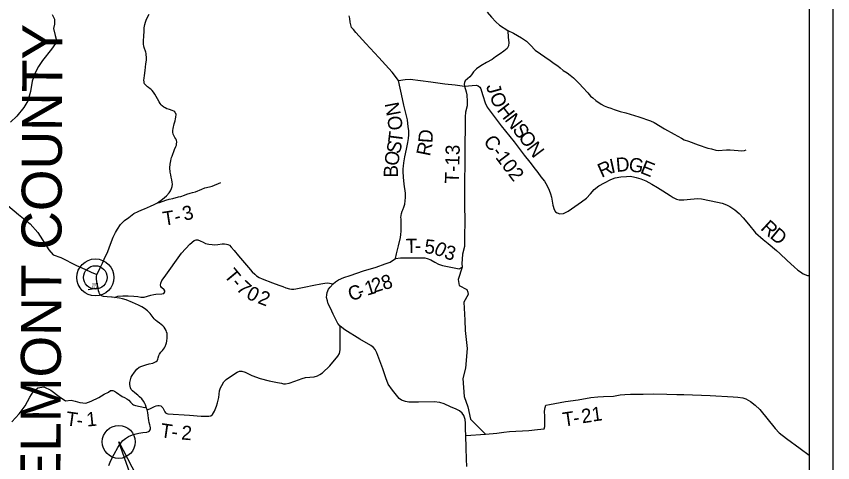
# Model space of a CAD drawing. Extents: x 0 to 2329303, y 0 to 694397.
# Drawn here: x 5.532 to 9, y 16.215 to 18.113 of the extents above; entities that cross this region are included whole.
import ezdxf

# ---------------------------------------------------------------- set-up
doc = ezdxf.new("R2010")
doc.units = 0
for name, color, linetype in [('GM_X_County', 7, 'Continuous'), ('GM_X_County_Road', 7, 'Continuous'), ('GM_X_County_Road_Text', 7, 'Continuous'), ('GM_X_State_Route', 7, 'Continuous'), ('GM_X_Township_Road', 7, 'Continuous'), ('GM_X_Township_Road_Text', 7, 'Continuous'), ('GM_X_Township_ROW', 7, 'Continuous'), ('GM_X_Township_Subdivision', 7, 'Continuous'), ('GM_X_Township_Subdivision_Text', 7, 'Continuous'), ('GM_X_Unincorporated', 7, 'Continuous'), ('SH_Data', 7, 'Continuous')]:
    doc.layers.add(name, color=color, linetype=linetype)

msp = doc.modelspace()

# ---------------------------------------------------------------- linework, layer by layer
at = {"layer": 'GM_X_County_Road'}
for points in [[(7.1555, 17.8397), (7.1292, 17.8753), (7.072, 17.9377), (7.0165, 17.9975), (6.9751, 18.0441), (6.964, 18.056), (6.9564, 18.0648), (6.9527, 18.0762), (6.9503, 18.0875), (6.9493, 18.1033), (6.9464, 18.1149)], [(7.446, 16.1983), (7.4453, 16.2296), (7.4436, 16.2777), (7.4424, 16.3304), (7.441, 16.3567), (7.4406, 16.3821), (7.4394, 16.3983), (7.4336, 16.4146), (7.4262, 16.4256), (7.4149, 16.4351), (7.4011, 16.4417), (7.3771, 16.4527), (7.3502, 16.4656), (7.3312, 16.4703), (7.3066, 16.4727), (7.2409, 16.4719), (7.2135, 16.4721), (7.1992, 16.4724), (7.1853, 16.4746), (7.169, 16.4809), (7.1588, 16.4877), (7.1472, 16.5019), (7.1309, 16.5225), (7.1123, 16.5487), (7.1018, 16.5754), (7.089, 16.613), (7.0634, 16.6822), (7.0561, 16.6952), (7.0499, 16.7041), (7.0386, 16.7129), (6.9915, 16.7405), (6.9285, 16.7802), (6.9078, 16.7952), (6.8975, 16.8071), (6.8912, 16.82), (6.8782, 16.8458), (6.8671, 16.8713), (6.857, 16.8906), (6.8537, 16.9026), (6.8505, 16.9169), (6.8512, 16.9282), (6.8533, 16.9385), (6.8557, 16.9451), (6.859, 16.952), (6.865, 16.9612), (6.8777, 16.9755), (6.8878, 16.9833), (6.9011, 16.9919), (6.9236, 17.0015), (6.9511, 17.01), (7.0076, 17.0297), (7.0613, 17.0466), (7.0998, 17.0601), (7.1197, 17.0679), (7.1429, 17.0828), (7.1471, 17.102), (7.1557, 17.1373), (7.1641, 17.1723), (7.1658, 17.1855), (7.1666, 17.1994), (7.1666, 17.2276), (7.1665, 17.2515), (7.1662, 17.2577), (7.1668, 17.266), (7.1683, 17.2735), (7.1711, 17.2845), (7.1737, 17.2902), (7.1784, 17.3012), (7.182, 17.314), (7.1844, 17.328), (7.1858, 17.342), (7.1855, 17.3612), (7.1805, 17.3984), (7.1765, 17.4282), (7.1754, 17.453), (7.1754, 17.4646), (7.1768, 17.4753), (7.1786, 17.4895), (7.1834, 17.515), (7.1896, 17.5471), (7.1958, 17.5767), (7.1981, 17.5927), (7.1991, 17.6081), (7.1993, 17.6265), (7.1975, 17.6425), (7.1936, 17.6725), (7.1848, 17.7115), (7.179, 17.7354), (7.169, 17.7814), (7.1629, 17.807), (7.1555, 17.8397)], [(7.1555, 17.8397), (7.184, 17.8445), (7.2059, 17.8446), (7.293, 17.8346), (7.3533, 17.8256), (7.3964, 17.8205), (7.4365, 17.8157), (7.4857, 17.8195), (7.4944, 17.8169), (7.5015, 17.8116), (7.5061, 17.804), (7.5087, 17.7936), (7.5147, 17.7752), (7.5243, 17.7446), (7.5329, 17.726), (7.5496, 17.7041), (7.5924, 17.6475), (7.6476, 17.5783), (7.69, 17.5222), (7.7135, 17.493), (7.7367, 17.463), (7.7477, 17.4482), (7.7609, 17.4303), (7.7762, 17.4117), (7.7877, 17.3924), (7.7957, 17.3733), (7.8016, 17.3577), (7.8053, 17.3435), (7.8107, 17.3098), (7.817, 17.2911), (7.8224, 17.2817), (7.8294, 17.2763), (7.8413, 17.273), (7.8563, 17.2746), (7.8758, 17.2835), (7.9331, 17.3234), (7.9547, 17.3388), (7.9711, 17.3571), (7.9869, 17.3766), (8.0072, 17.3914), (8.0305, 17.405), (8.0572, 17.4193), (8.0765, 17.4251), (8.0999, 17.4296), (8.1238, 17.4321), (8.1396, 17.4326), (8.1536, 17.4307), (8.1647, 17.4276), (8.1857, 17.421), (8.2059, 17.4129), (8.2312, 17.3994), (8.2562, 17.3852), (8.2791, 17.3703), (8.3092, 17.3503), (8.322, 17.3422), (8.3373, 17.3346), (8.3481, 17.3318), (8.3684, 17.3318), (8.396, 17.3356), (8.4273, 17.3373), (8.4423, 17.3359), (8.5114, 17.3226), (8.5307, 17.3183), (8.5488, 17.3108), (8.5628, 17.3041), (8.5839, 17.2896), (8.6027, 17.2743), (8.6193, 17.2555), (8.6419, 17.2286), (8.6724, 17.1923), (8.7045, 17.1629), (8.7253, 17.1465), (8.7613, 17.1171), (8.776, 17.1034), (8.8073, 17.0739), (8.8363, 17.048), (8.8527, 17.0337), (8.8632, 17.0257), (8.8746, 17.0183), (8.8934, 17.0111), (8.9, 17.0099)], [(5.4966, 17.3082), (5.5414, 17.2703), (5.5919, 17.2302), (5.6241, 17.1939), (5.6708, 17.1199), (5.6888, 17.0991), (5.7217, 17.0865), (5.7881, 17.0526), (5.8233, 17.0374), (5.8508, 17.0243), (5.8747, 17.0143)]]:
    msp.add_lwpolyline(points, dxfattribs=at)
at = {"layer": 'GM_X_State_Route'}
for points in [[(6.0651, 17.2894), (6.0765, 17.2943), (6.1027, 17.3056), (6.118, 17.3124), (6.132, 17.3197), (6.1533, 17.3345), (6.1701, 17.3491), (6.1819, 17.3613), (6.1875, 17.3706), (6.1916, 17.3804), (6.194, 17.3883), (6.1954, 17.3986), (6.1947, 17.4069), (6.1929, 17.4168), (6.1901, 17.4287), (6.1881, 17.4387), (6.1863, 17.4504), (6.1852, 17.4679), (6.1861, 17.4839), (6.1871, 17.4916), (6.1883, 17.4987), (6.1902, 17.5066), (6.1918, 17.512), (6.1938, 17.5181), (6.205, 17.5465), (6.2099, 17.5593), (6.2123, 17.5653), (6.2135, 17.5707), (6.2139, 17.5772), (6.2127, 17.5854), (6.2098, 17.5922), (6.2063, 17.5979), (6.2018, 17.6057), (6.1993, 17.6109), (6.1976, 17.6205), (6.1975, 17.6264), (6.199, 17.6358), (6.2034, 17.6553), (6.2065, 17.6686), (6.2086, 17.6773), (6.2103, 17.6835), (6.211, 17.6951), (6.2098, 17.6988), (6.2076, 17.7027), (6.2055, 17.7058), (6.2013, 17.7088), (6.195, 17.7118), (6.1836, 17.716), (6.1722, 17.7197), (6.1643, 17.7231), (6.1584, 17.7268), (6.1518, 17.7313), (6.1474, 17.7357), (6.1432, 17.7416), (6.1386, 17.749), (6.1319, 17.7617), (6.1215, 17.7819), (6.1147, 17.7904), (6.1097, 17.7967), (6.105, 17.8008), (6.1005, 17.8047), (6.0944, 17.8094), (6.0901, 17.8125), (6.0862, 17.8157), (6.0822, 17.8193), (6.0795, 17.8225), (6.0774, 17.826), (6.0759, 17.8296), (6.0749, 17.8336), (6.0747, 17.8411), (6.0753, 17.8499), (6.0765, 17.8605), (6.0793, 17.8818), (6.083, 17.9101), (6.0847, 17.9256), (6.0848, 17.9389), (6.0842, 17.9489), (6.0837, 17.9545), (6.0823, 17.9601), (6.0755, 17.9799), (6.0742, 17.987), (6.0732, 17.9931), (6.0731, 17.9986), (6.0732, 18.0081), (6.074, 18.0279), (6.0753, 18.0495), (6.0761, 18.0642), (6.0785, 18.0779), (6.0813, 18.0874), (6.0841, 18.0958), (6.0873, 18.103), (6.0973, 18.1213)], [(5.9391, 16.9181), (5.9371, 16.9183), (5.9187, 16.9194), (5.9029, 16.9218), (5.8949, 16.9241), (5.8894, 16.928), (5.8859, 16.9322), (5.8837, 16.9377), (5.8815, 16.9457), (5.8796, 16.9565), (5.8771, 16.9707), (5.8742, 16.9833), (5.873, 16.9963), (5.8735, 17.0057), (5.8747, 17.0143), (5.8819, 17.0277), (5.8899, 17.046), (5.898, 17.0625), (5.9058, 17.0804), (5.9206, 17.113), (5.927, 17.1279), (5.933, 17.1442), (5.944, 17.1741), (5.9538, 17.1936), (5.962, 17.2076), (5.975, 17.2273), (5.9836, 17.2365), (5.9919, 17.2439), (6.01, 17.2576), (6.0321, 17.2735), (6.0504, 17.2832), (6.0651, 17.2894)], [(5.9253, 16.2032), (5.9332, 16.2243), (5.9477, 16.2511), (5.9633, 16.279), (5.9747, 16.2961), (5.9854, 16.3091), (5.9957, 16.3176), (6.0087, 16.3258), (6.0253, 16.3327), (6.0418, 16.3376), (6.0534, 16.3396), (6.0698, 16.3427), (6.0872, 16.3449), (6.0942, 16.3473), (6.0987, 16.35), (6.1016, 16.3542), (6.1021, 16.359), (6.1017, 16.3631), (6.1007, 16.3699), (6.0994, 16.3754), (6.0969, 16.3853), (6.0953, 16.3945), (6.094, 16.4045), (6.0923, 16.4158), (6.0905, 16.428), (6.0884, 16.4393), (6.0859, 16.4469), (6.0846, 16.4504), (6.0817, 16.46), (6.078, 16.4667), (6.0723, 16.4766), (6.0649, 16.4861), (6.0559, 16.4945), (6.0482, 16.5013), (6.0359, 16.5117), (6.0254, 16.5206), (6.0208, 16.5262), (6.0174, 16.5328), (6.0159, 16.5398), (6.015, 16.5472), (6.0151, 16.5562), (6.0172, 16.567), (6.0208, 16.5779), (6.0245, 16.5857), (6.0338, 16.5995), (6.045, 16.6122), (6.0543, 16.6203), (6.0652, 16.6256), (6.0828, 16.6312), (6.0972, 16.6345), (6.113, 16.6385), (6.1206, 16.6414), (6.1259, 16.6444), (6.1301, 16.6483), (6.1334, 16.6543), (6.1346, 16.6605), (6.138, 16.6701), (6.1401, 16.6756), (6.1458, 16.684), (6.1529, 16.692), (6.1614, 16.703), (6.1651, 16.7091), (6.1693, 16.7197), (6.1704, 16.7245), (6.1717, 16.7317), (6.1736, 16.7462), (6.1736, 16.7521), (6.1733, 16.7584), (6.1728, 16.7637), (6.171, 16.7705), (6.1684, 16.7766), (6.1647, 16.7841), (6.1599, 16.7908), (6.1553, 16.7959), (6.1476, 16.8029), (6.141, 16.8081), (6.1306, 16.8153), (6.1241, 16.8201), (6.1186, 16.8262), (6.1139, 16.8317), (6.1098, 16.8371), (6.1008, 16.8495), (6.0896, 16.861), (6.0776, 16.87), (6.0652, 16.8775), (6.051, 16.8841), (6.0262, 16.8962), (5.9995, 16.9066), (5.9831, 16.9118), (5.9703, 16.9145), (5.9494, 16.9174), (5.9391, 16.9181)]]:
    msp.add_lwpolyline(points, dxfattribs=at)
at = {"layer": 'GM_X_Township_Road'}
for points in [[(5.6849, 18.1207), (5.6941, 18.1002), (5.6953, 18.0798), (5.6909, 18.0608), (5.6977, 18.0306), (5.7023, 18.0151), (5.699, 17.9965), (5.6812, 17.9722), (5.6434, 17.9242), (5.6272, 17.8987), (5.6126, 17.8717), (5.6, 17.8367), (5.5921, 17.7931), (5.5812, 17.753), (5.5643, 17.725), (5.5345, 17.6878), (5.5083, 17.6623)], [(7.5331, 18.1304), (7.5504, 18.1095), (7.5688, 18.0886), (7.5855, 18.0749), (7.6208, 18.0528), (7.6448, 18.0405), (7.6784, 18.0214), (7.699, 18.0067), (7.7163, 17.9894), (7.7358, 17.9688), (7.7994, 17.9247), (7.8176, 17.9119), (7.8319, 17.9022), (7.8422, 17.893), (7.8559, 17.8816), (7.8724, 17.8716), (7.8853, 17.8623), (7.8992, 17.8507), (7.9131, 17.8366), (7.9241, 17.8259), (7.9385, 17.8098), (7.9595, 17.7866), (7.972, 17.7733), (7.981, 17.7654), (7.9946, 17.7544), (8.0162, 17.7388), (8.0288, 17.7316), (8.0432, 17.7256), (8.0572, 17.7218), (8.0725, 17.7169), (8.0976, 17.7084), (8.1216, 17.702), (8.1763, 17.6853), (8.2263, 17.6684), (8.2415, 17.6611), (8.2862, 17.6335), (8.3272, 17.6113), (8.3583, 17.5946), (8.3696, 17.588), (8.3869, 17.5818), (8.4288, 17.5659), (8.4693, 17.5525), (8.4851, 17.5489), (8.5034, 17.5436), (8.5139, 17.5427), (8.5495, 17.5455), (8.5644, 17.5451), (8.598, 17.5427), (8.6147, 17.5412), (8.6255, 17.5419), (8.6321, 17.5453)], [(7.6208, 18.0528), (7.6213, 18.0225), (7.624, 18.0016), (7.6234, 17.9869), (7.618, 17.9751), (7.6031, 17.9642), (7.5881, 17.953), (7.5682, 17.9402), (7.5538, 17.9288), (7.5289, 17.9162), (7.5054, 17.9026), (7.4865, 17.8897), (7.4746, 17.8758), (7.466, 17.8639), (7.4584, 17.855), (7.4482, 17.8462), (7.439, 17.8383), (7.4362, 17.8317), (7.4341, 17.8238), (7.4365, 17.8157), (7.4432, 17.7921), (7.4457, 17.7783), (7.448, 17.7503), (7.4477, 17.7318), (7.4407, 17.705), (7.4386, 17.6851), (7.4374, 17.522), (7.4369, 17.4778), (7.4368, 17.4192), (7.4366, 17.3849)], [(6.132, 17.3197), (6.1406, 17.3203), (6.1676, 17.3303), (6.1819, 17.3346), (6.1968, 17.3383), (6.2218, 17.3445), (6.231, 17.347), (6.2474, 17.3527), (6.2568, 17.3563), (6.2708, 17.36), (6.2814, 17.363), (6.2938, 17.3668), (6.3198, 17.3777), (6.3338, 17.3832), (6.3525, 17.3882), (6.3637, 17.3897), (6.4006, 17.4059)], [(7.4366, 17.3849), (7.4366, 17.3784), (7.4368, 17.3136), (7.4371, 17.2384), (7.4367, 17.1789), (7.4355, 17.1333), (7.4283, 17.101), (7.4263, 17.0805), (7.4251, 17.062), (7.4268, 17.0456)], [(5.9494, 16.9174), (5.964, 16.9226), (5.9848, 16.9242), (6.008, 16.9243), (6.031, 16.922), (6.048, 16.9213), (6.0619, 16.9182), (6.0751, 16.9182), (6.0893, 16.9224), (6.1033, 16.9266), (6.1162, 16.9303), (6.1252, 16.9311), (6.1507, 16.9321), (6.1594, 16.9345), (6.1638, 16.9406), (6.163, 16.9453), (6.1599, 16.9502), (6.1492, 16.9593), (6.1462, 16.9644), (6.1445, 16.9695), (6.1461, 16.9774), (6.1506, 16.9893), (6.1608, 17.0025), (6.2336, 17.1058), (6.2693, 17.1435), (6.2873, 17.1587), (6.2963, 17.1621), (6.3039, 17.1615), (6.3127, 17.1573), (6.3257, 17.152), (6.3365, 17.147), (6.3496, 17.1436), (6.3648, 17.1421), (6.3758, 17.1416), (6.389, 17.1426), (6.4064, 17.1445), (6.4174, 17.1451), (6.4249, 17.1442), (6.4315, 17.1421), (6.4376, 17.1389), (6.4378, 17.1388)], [(6.4378, 17.1388), (6.4455, 17.1314), (6.4571, 17.1173), (6.4759, 17.0936), (6.5182, 17.0448), (6.5348, 17.0263), (6.545, 17.0167), (6.5529, 17.0097), (6.5644, 17.0019), (6.577, 16.9957), (6.6207, 16.9794), (6.6479, 16.9691), (6.6638, 16.9637), (6.6776, 16.9587), (6.6927, 16.9543), (6.702, 16.9522), (6.7106, 16.9529), (6.7196, 16.9545)], [(7.1429, 17.0828), (7.1637, 17.0862), (7.2218, 17.086), (7.2671, 17.0855), (7.2776, 17.0833), (7.2929, 17.0773), (7.3097, 17.0675), (7.3259, 17.0594), (7.3433, 17.0537), (7.4138, 17.0394), (7.4268, 17.0456)], [(6.7196, 16.9545), (6.7335, 16.957), (6.7552, 16.9605), (6.796, 16.9695), (6.8265, 16.9753), (6.8431, 16.9778), (6.8542, 16.9789), (6.8777, 16.9755)], [(6.172, 16.4238), (6.1766, 16.4222), (6.2685, 16.4161), (6.3169, 16.4131), (6.3406, 16.4123), (6.3505, 16.4122), (6.359, 16.4143), (6.3656, 16.4197), (6.3743, 16.4339), (6.3827, 16.4553), (6.3868, 16.4687), (6.392, 16.4915), (6.3959, 16.5198), (6.3998, 16.533), (6.4049, 16.5427), (6.4136, 16.5583), (6.4231, 16.5681), (6.4549, 16.59), (6.4705, 16.5999), (6.481, 16.6032), (6.4905, 16.6036), (6.5048, 16.599), (6.5335, 16.5859), (6.5683, 16.5728), (6.6066, 16.5626), (6.642, 16.5559), (6.6593, 16.5523), (6.668, 16.5505), (6.6753, 16.5496), (6.6914, 16.5529), (6.715, 16.5609), (6.7461, 16.5721), (6.7614, 16.5766), (6.7974, 16.58), (6.8114, 16.5839), (6.8214, 16.5894), (6.8326, 16.5969), (6.8637, 16.6262), (6.8982, 16.6671), (6.9055, 16.6791), (6.9086, 16.6939), (6.9078, 16.7952)], [(5.5129, 16.3882), (5.544, 16.4219), (5.5699, 16.4562), (5.5897, 16.4926), (5.6036, 16.516), (5.6242, 16.5324), (5.6497, 16.5366), (5.679, 16.5237), (5.715, 16.4955), (5.7413, 16.4777), (5.7656, 16.4802), (5.7826, 16.4769), (5.8028, 16.4708), (5.8282, 16.4682), (5.8507, 16.4759), (5.8829, 16.4924), (5.9056, 16.5065), (5.924, 16.5148), (5.9324, 16.5214), (5.9421, 16.5218), (5.9491, 16.5192), (5.9574, 16.5128), (5.9817, 16.4961), (5.9919, 16.4919), (6.0019, 16.4865), (6.0102, 16.4806), (6.018, 16.4715), (6.0218, 16.4678), (6.0256, 16.464), (6.0307, 16.4605), (6.038, 16.4577), (6.0582, 16.4536), (6.0784, 16.4497), (6.0846, 16.4504)], [(7.4424, 16.3304), (7.5255, 16.3355), (7.5729, 16.3397), (7.6026, 16.3445), (7.6273, 16.3477), (7.7091, 16.3519), (7.7463, 16.3562), (7.7742, 16.3586), (7.7777, 16.3686), (7.7776, 16.4114), (7.7754, 16.4337), (7.7782, 16.4492), (7.7812, 16.4586), (7.7966, 16.4619), (7.8654, 16.4747), (7.9189, 16.4822), (7.9731, 16.4919), (8.0021, 16.4951), (8.0268, 16.4963), (8.0685, 16.4982), (8.0973, 16.5025), (8.117, 16.5051), (8.1411, 16.5059), (8.1953, 16.5064), (8.2392, 16.5073), (8.2954, 16.5057), (8.3385, 16.5041), (8.3684, 16.5044), (8.4796, 16.501), (8.578, 16.4949), (8.5974, 16.4933), (8.6188, 16.49), (8.6311, 16.4864), (8.6511, 16.4745), (8.6714, 16.4597), (8.6913, 16.4408), (8.7563, 16.36), (8.7731, 16.3416), (8.8039, 16.3174), (8.8625, 16.2749), (8.9, 16.2466)], [(6.0884, 16.4393), (6.0998, 16.4441), (6.1189, 16.4533), (6.1266, 16.4562), (6.1332, 16.4575), (6.1397, 16.4579), (6.1456, 16.4566), (6.1506, 16.4526), (6.1543, 16.4481), (6.1629, 16.4304), (6.1664, 16.427), (6.1711, 16.4242), (6.172, 16.4238)]]:
    msp.add_lwpolyline(points, dxfattribs=at)
at = {"layer": 'GM_X_Township_ROW'}
msp.add_lwpolyline([(7.4268, 17.0456), (7.4086, 16.9941), (7.4128, 16.9686), (7.4465, 16.9506), (7.4506, 16.94), (7.4522, 16.9294), (7.434, 16.8971), (7.437, 16.8205), (7.4391, 16.7772), (7.4478, 16.7002), (7.441, 16.6162), (7.4295, 16.5728), (7.4349, 16.4961), (7.451, 16.4526), (7.4615, 16.3997), (7.5255, 16.3355)], dxfattribs=at)
at = {"layer": 'GM_X_Township_Subdivision'}
msp.add_lwpolyline([(5.8796, 16.9565), (5.8376, 16.9491)], dxfattribs=at)
at = {"layer": 'GM_X_Unincorporated'}
for radius in [0.0786, 0.0498]:
    msp.add_circle((5.8682, 17.0024), radius, dxfattribs=at)
at = {"layer": 'SH_Data'}
for points in [[(2, 21), (9, 21), (9, 14), (2, 14)], [(2.1, 20.9), (8.9, 20.9), (8.9, 14.1), (2.1, 14.1)], [(6.4087, 15.4552), (6.2687, 15.4552), (5.9675, 16.303)]]:
    msp.add_lwpolyline(points, close=True, dxfattribs=at)
msp.add_circle((5.9675, 16.303), 0.07, dxfattribs=at)

# ---------------------------------------------------------------- texts
at = {"layer": 'GM_X_County'}
msp.add_text('BELMONT COUNTY', height=0.17, rotation=89.7416, dxfattribs=at).set_placement((5.7189, 15.9576))
at = {"layer": 'GM_X_County_Road_Text'}
for s, rotation, p in [('J', 285.8488, (7.5273, 17.8168)), ('O', 293.9497, (7.5407, 17.774)), ('N', 101.0152, (7.1663, 17.6957)), ('H', 308.082, (7.5714, 17.7124)), ('O', 97.7259, (7.175, 17.6319)), ('N', 306.9096, (7.6045, 17.6717)), ('S', 306.9098, (7.6369, 17.63)), ('T', 82.8184, (7.1705, 17.5703)), ('D', 86.276, (7.2995, 17.5722)), ('O', 306.9087, (7.6618, 17.598)), ('S', 77.4903, (7.1614, 17.5246)), ('C-102', 307.2527, (7.5137, 17.5796)), ('N', 306.9107, (7.697, 17.5514)), ('R', 78.483, (7.2894, 17.5151)), ('O', 79.1637, (7.1525, 17.473)), ('D', 5.0153, (8.0818, 17.4505)), ('G', 349.0841, (8.13, 17.4561)), ('R', 24.1434, (8.0184, 17.4252)), ('I', 12.6313, (8.06, 17.445)), ('E', 337.9897, (8.179, 17.4478)), ('B', 89.5355, (7.1531, 17.4266)), ('R', 317.2388, (8.6906, 17.2083)), ('D', 320.3013, (8.73, 17.1733)), ('2', 17.2927, (7.0513, 16.9364)), ('8', 18.3239, (7.094, 16.9476)), ('C', 18.0067, (6.9524, 16.9007)), ('1', 16.8925, (7.0222, 16.9242)), ('-', 16.8907, (6.99, 16.9142))]:
    msp.add_text(s, height=0.06, rotation=rotation, dxfattribs=at).set_placement(p)
at = {"layer": 'GM_X_Township_Road_Text'}
for s, rotation, p in [('T-13', 88.5881, (7.4123, 17.4012)), ('3', 15.3035, (6.2468, 17.2422)), ('T', 8.7204, (6.159, 17.2216)), ('-', 15.7151, (6.211, 17.2309)), ('T', 1.1122, (7.1867, 17.1063)), ('5', 354.1641, (7.2639, 17.1057)), ('-', 359.0437, (7.2246, 17.1079)), ('0', 332.9602, (7.3016, 17.1055)), ('3', 343.6498, (7.3461, 17.085)), ('T', 309.7167, (6.4118, 17.0096)), ('7', 316.9869, (6.4631, 16.9511)), ('-', 310.1851, (6.4414, 16.9752)), ('0', 332.1522, (6.5048, 16.9165)), ('2', 339.151, (6.5544, 16.8941)), ('2', 8.1721, (7.9366, 16.3818)), ('1', 7.6175, (7.98, 16.3893)), ('T', 352.1563, (5.7401, 16.3737)), ('1', 5.7931, (5.8327, 16.3679)), ('T', 8.285, (7.8572, 16.3679)), ('-', 8.2675, (7.9015, 16.3751)), ('-', 353.2577, (5.7859, 16.3681)), ('T', 351.8581, (6.1414, 16.3236)), ('2', 355.4675, (6.2315, 16.3134)), ('-', 355.1814, (6.1897, 16.3176))]:
    msp.add_text(s, height=0.06, rotation=rotation, dxfattribs=at).set_placement(p)
at = {"layer": 'GM_X_Township_Subdivision_Text'}
for s, rotation, p in [('3RD', 8.7465, (5.8538, 16.9664)), ('ALY', 7.8529, (5.8538, 16.9546))]:
    msp.add_text(s, height=0.01, rotation=rotation, dxfattribs=at).set_placement(p)

doc.saveas('drawing.dxf')
